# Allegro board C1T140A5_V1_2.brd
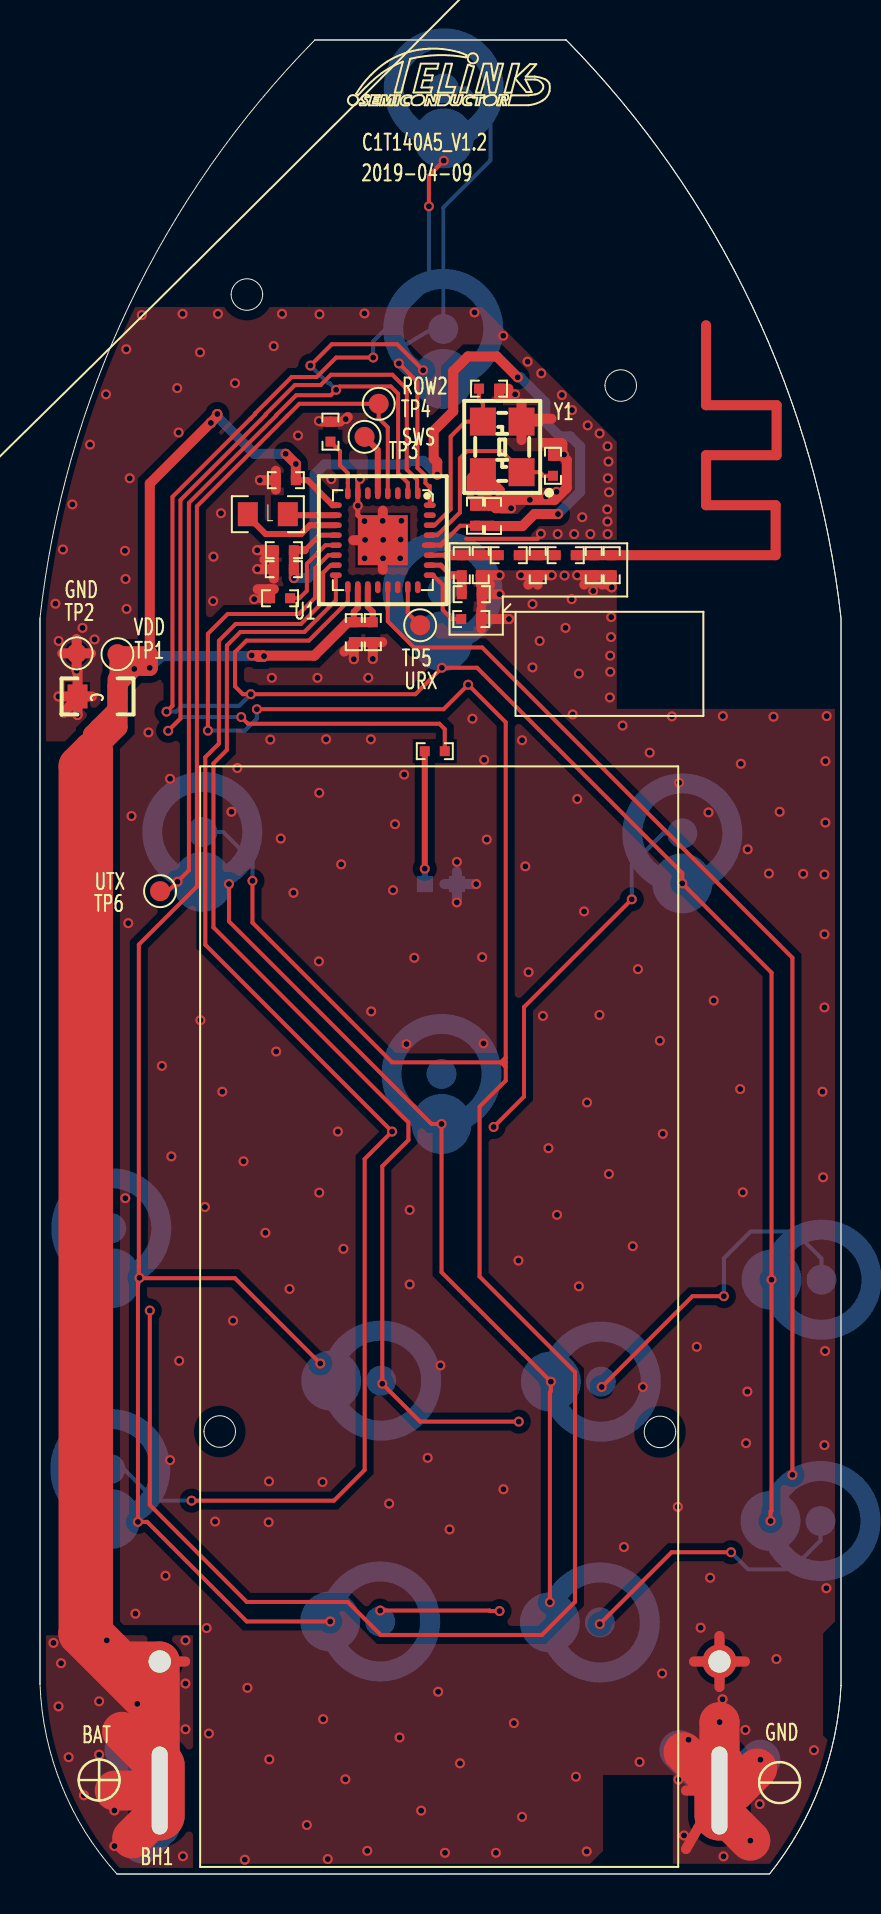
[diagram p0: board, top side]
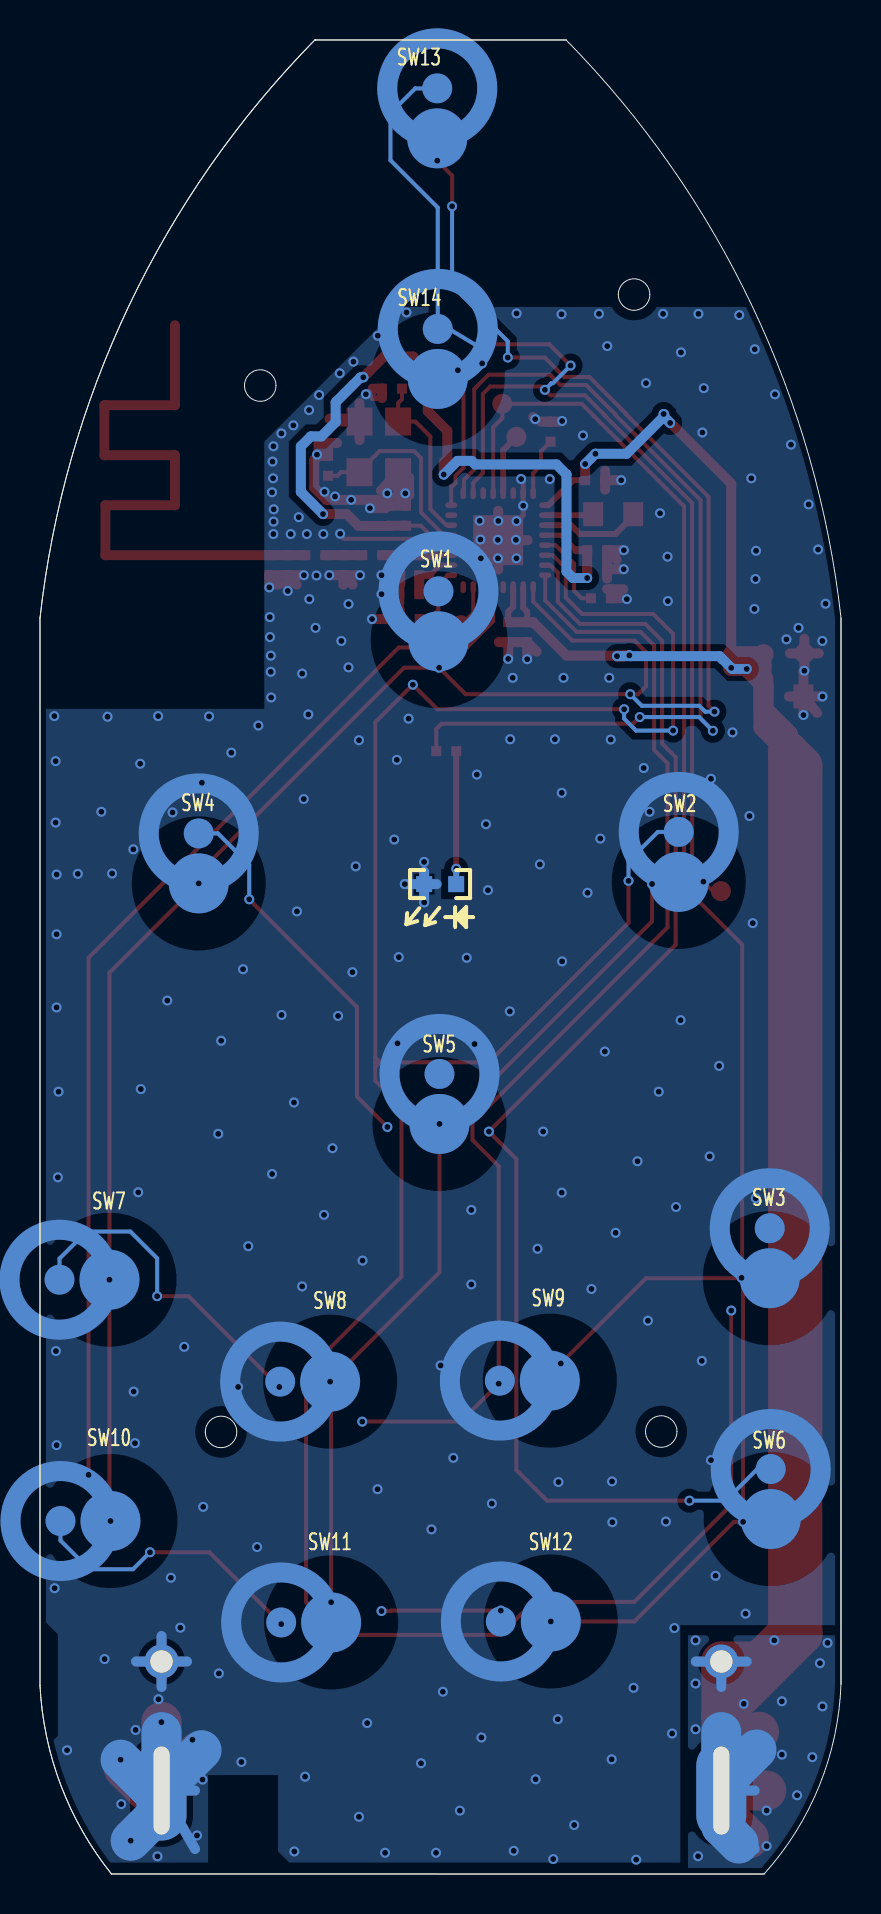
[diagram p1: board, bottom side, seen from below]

Outline 40.07 x 91.71 mm; copper layers: TOP, BOTTOM. Coordinates in mm from the lower left corner of the outline.
Outline path: 0,62.8 0,9.5 ; 0,62.8 arc(4.45,78.41) 13.75,91.71 ; 0,62.8 0,9.5 ; 0,9.5 arc(1.09,4.41) 3.85,0 ; 13.75,91.71 26.29,91.71 ; 13.75,91.71 26.29,91.71 ; 3.85,0 36.49,0 ; 3.85,0 36.49,0 ; 36.49,0 arc(39.02,4.43) 40.07,9.42 ; 36.49,0 arc(39.02,4.43) 40.07,9.42 ; 26.29,91.71 26.32,91.71 ; 26.29,91.71 26.32,91.71 ; 26.32,91.71 arc(35.62,78.41) 40.07,62.8 ; 26.32,91.71 arc(35.62,78.41) 40.07,62.8 ; 40.07,62.8 40.07,9.42 ; 40.07,62.8 40.07,9.42 ; 8.21,22.13 arc(8.99,22.91) 9.78,22.13 arc(8.99,21.34) 8.21,22.13 ; 9.56,78.98 arc(10.35,79.77) 11.14,78.98 arc(10.35,78.2) 9.56,78.98 ; 28.26,74.43 arc(29.05,75.22) 29.84,74.43 arc(29.05,73.65) 28.26,74.43 ; 30.23,22.11 arc(31.01,22.9) 31.8,22.11 arc(31.01,21.32) 30.23,22.11

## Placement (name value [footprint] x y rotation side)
BH1  BATT CON 2xAAA  [BAT]  5.99 4.17 0 top
C1  0.1uF  [0402]  21.76 67.92 270 top
C2  2.2uF  [0402]  22.66 67.91 270 top
C3  2.7pF  [0402]  22.05 65.45 90 top
C4  2pF  [0402]  24.9 65.45 90 top
C5  0.5pF  [0402]  27.7 65.45 90 top
C6  220pF  [0402]  23.45 65.95 0 top
C7  18pF  [0402]  21.6 64 0 top
C8  1uF  [0402]  21.57 62.76 0 top
C9  1uF  [0402]  16.65 62.1 270 top
C10  1uF  [0402]  14.53 72.13 270 top
C11  1uF  [0402]  15.7 62.1 270 top
C12  NC  [0402]  25.66 70.42 90 top
C13  NC  [0402]  22.46 74.28 0 top
C14  1uF  [0402]  12.3 69.7 180 top
C15  1uF  [0402]  12.01 63.8 180 top
C16  0.1uF  [0402]  12.2 66.2 180 top
C17  1uF  [0402]  12.2 65.25 180 top
C19  22uF  [0805C]  2.88 58.89 180 top
D1  LED  [0603-LED]  20.05 49.5 0 bottom
L1  1.3nH  [0402]  21.1 65.45 90 top
L2  3.3nH  [0402]  26.3 65.95 0 top
L3  3.3nH  [0402]  28.6 65.45 270 top
L4  47uH  [0805L]  11.4 68 0 top
R1  1K  [0402]  19.75 56.15 0 top
SW1  SW2PIN_2.2x4.0  [SW_OUT6_IN3_NEW]  20.14 61.64 180 bottom
SW2  SW2PIN_2.2x4.0  [SW_OUT6_IN3_NEW]  8.12 49.61 180 bottom
SW3  SW2PIN_2.2x4.0  [SW_OUT6_IN3_NEW]  3.57 29.79 180 bottom
SW4  SW2PIN_2.2x4.0  [SW_OUT6_IN3_NEW]  32.13 49.54 180 bottom
SW5  SW2PIN_2.2x4.0  [SW_OUT6_IN3_NEW]  20.09 37.51 180 bottom
SW6  SW2PIN_2.2x4.0  [SW_OUT6_IN3_NEW]  3.52 17.75 180 bottom
SW7  SW2PIN_2.2x4.0  [SW_OUT6_IN3_NEW]  36.59 29.72 90 bottom
SW8  SW2PIN_2.2x4.0  [SW_OUT6_IN3_NEW]  25.56 24.62 90 bottom
SW9  SW2PIN_2.2x4.0  [SW_OUT6_IN3_NEW]  14.57 24.67 90 bottom
SW10  SW2PIN_2.2x4.0  [SW_OUT6_IN3_NEW]  36.54 17.65 90 bottom
SW11  SW2PIN_2.2x4.0  [SW_OUT6_IN3_NEW]  25.51 12.58 90 bottom
SW12  SW2PIN_2.2x4.0  [SW_OUT6_IN3_NEW]  14.52 12.63 90 bottom
SW13  SW2PIN_2.2x4.0  [SW_OUT6_IN3_NEW]  20.2 86.79 180 bottom
SW14  SW2PIN_2.2x4.0  [SW_OUT6_IN3_NEW]  20.17 74.76 180 bottom
TP1  VDD  [TP100]  3.87 61 0 top
TP2  GND  [TP100]  1.83 61.04 0 top
TP3  SWS  [TP100]  16.24 71.87 0 top
TP4  Row2  [TP100]  16.94 73.52 0 top
TP5  URX  [TP100]  19.02 62.45 0 top
TP6  UTX  [TP100]  6.01 49.15 0 top
U1  TLSR8258F512ET32  [QFN_5X5_32PIN_0P5_2P50X2P50]  17.15 66.7 270 top
Y1  24Mhz - 12pf - +/-20ppm  [OSCCC250X320X110]  23.12 71.37 180 top

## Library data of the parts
BH1 = Chicony Battery conn 2xAA_0
C1 C6 C9 C11 C14-C16 = C1005X5R1C104K
C2 = C1005X5R1A225K
C3-C5 = C1608_NC
C7 = C1005C0G1H100D
C8 C10 = C1005X5R1C105K
C12 C13 = C1005_NC
C17 = C1005X5R0J475M
C19 = C2012X5R1A226M
D1 = 0603D_Red
L1 L2 = MLK1608_000R
L3 = MLK1005_000R
L4 = IND_0
R1 = RS0402K472JT
SW1 = SW2PIN_8
SW2-SW4 SW6-SW14 = SW2PIN_4
SW5 = SW2PIN_5
TP1-TP6 = TestPad100
U1 = TLSR8258F512ET32
Y1 = OSC_25x32_4pin: Tolerance: RichardLC

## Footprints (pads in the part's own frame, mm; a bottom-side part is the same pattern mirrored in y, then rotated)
0402
  rect 0.5x0.5 smd: 1(-0.5,0) 2(0.5,0)
0603-LED
  rect 0.8x0.8 smd: A(-0.8,0) C(0.8,0)
0805C
  rect 1x1.2 smd: 1(-1,0) 2(1,0)
0805L
  rect 1x1.2 smd: 1(-1,0) 2(1,0)
BAT
  oval 2.5x5 hole 0.8x4.4: 1(0,0) 2(28,0)
  round 1.7 hole 1.118: 3(0,6.454) 4(28,6.454)
OSCCC250X320X110
  rect 1.3x1.4 smd: 1(-0.965,1.265) 2(-0.965,-1.265) 3(0.965,-1.265) 4(0.965,1.265)
QFN_5X5_32PIN_0P5_2P50X2P50
  oval 0.6x0.28 smd: 1(-2.35,1.75) 2(-2.35,1.25) 3(-2.35,0.75) 4(-2.35,0.25) 5(-2.35,-0.25) 6(-2.35,-0.75) 7(-2.35,-1.25) 8(-2.35,-1.75) 17(2.35,-1.75) 18(2.35,-1.25) 19(2.35,-0.75) 20(2.35,-0.25) 21(2.35,0.25) 22(2.35,0.75) 23(2.35,1.25) 24(2.35,1.75)
  oval 0.28x0.6 smd: 9(-1.75,-2.35) 10(-1.25,-2.35) 11(-0.75,-2.35) 12(-0.25,-2.35) 13(0.25,-2.35) 14(0.75,-2.35) 15(1.25,-2.35) 16(1.75,-2.35) 25(1.75,2.35) 26(1.25,2.35) 27(0.75,2.35) 28(0.25,2.35) 29(-0.25,2.35) 30(-0.75,2.35) 31(-1.25,2.35) 32(-1.75,2.35)
  rect 2.5x2.5 smd: 33(0,0)
SW_OUT6_IN3_NEW
  round 3 smd: 1(0,0)
  custom 1.5x1.5 smd: 2(0,2.5)
TP100
  round 1 smd: 1(0,0)

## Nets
1V2: C1.2 C2.2 C16.1 C17.1 U1.12(VDD1V2) U1.28(AVDD1V2)
GND: BH1.2(NEG) BH1.4(NEG1) C1.1 C2.1 C3.1 C4.1 C5.1 C7.2 C8.2 C9.2 C10.1 C11.2 C12.2 C13.2 C14.2 C15.2 C16.2 C17.2 C19.2 D1.C(CATHODE) L3.2 TP2.1(TP) U1.7(DVSS) U1.33(GND) Y1.2 Y1.4
TL_COL0: SW1.2 SW2.2 SW3.2 U1.14(SDMP0/P4/B[4])
TL_COL1: SW4.2 SW5.2 SW6.2 U1.15(SDMN0/P5/B[5])
TL_COL2: SW7.2 SW8.2 SW9.2 U1.16(SDMP1/DI/URTS/B[6])
TL_COL3: SW10.2 SW11.2 SW12.2 U1.21(I2C_SCK/P1N/P0/C[1])
TL_COL4: SW13.2 SW14.2 U1.32(P1N/I2S_SDI/7816_TRX/D[3])
TL_LED: R1.2 U1.1(SWM/I2S_SDO/P2N/D[4])
TL_ROW0: SW1.1 SW4.1 SW7.1 SW10.1 SW13.1 U1.17(SDMN1/DO/URX/B[7])
TL_ROW1: SW2.1 SW5.1 SW8.1 SW11.1 SW14.1 TP6.1(TP) U1.2(CK/I2S_BCK/7816_TRX/D[7])
TL_ROW2: SW3.1 SW6.1 SW9.1 SW12.1 TP4.1(TP) U1.4(DMIC_CLK/7816_CLK/I2S_CLK/A[1])
TL_SWS: TP3.1(TP) U1.5(SWS/URTS/A[7])
TL_URX: TP5.1(TP) U1.23(P1/URX/I2C_SCK/32KIN/C[3])
TL_VDD3: BH1.1(POS) BH1.3(POS1) C9.1 C11.1 C14.1 C19.1 TP1.1(TP) U1.9(VDD_IO) U1.18(VDD3) U1.19(VDDIO_AMS)
TL_XC01: C12.1 U1.29(XC1) Y1.1
TL_XC02: C13.1 U1.30(XC2) Y1.3
N21091199: C3.2 C6.1 L1.2 U1.27(ANT)
N21091201: C7.1 L1.1 U1.26(VANT)
N21091237: C5.2 L2.2 L3.1
N21091295: C4.2 C6.2 L2.1
N21091335: C8.1 U1.25(RESETB)
N21091386: C10.2 U1.8(VDD1V)
N21091449: L4.1 U1.11(VDCDC)
N21091455: L4.2 U1.10(VDCDC_SW)
N21091487: C15.1 U1.13(VDD_F)
N21100596: D1.A(ANODE) R1.1

Pads without a net: U1 3 6 20 22 24 31

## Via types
v1: diameter 0.5, hole 0.3, TOP to BOTTOM, 315 vias

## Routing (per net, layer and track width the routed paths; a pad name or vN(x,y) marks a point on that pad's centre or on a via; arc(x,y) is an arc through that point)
1V2: length 42.5
  TOP w0.2: C1.2 21.02,67.42 20.22,66.63
  TOP w0.25: 13.25,66.2 14,66.95 U1.12 ; 19.22,66.45 U1.28 20.04,66.45 20.22,66.63
  TOP w0.4: 13.25,66.2 C16.1
  TOP w0.5: v1(12.7,64.81) C17.1 C16.1 ; v1(23.89,74.85) 22.85,75.89 21.4,75.89 20.67,75.15 20.67,73.15 19.69,72.17 19.69,70.78 19.87,70.6 v1(19.87,69.98) ; C1.2 22.65,67.42 C2.2 24.13,67.41 24.73,68.01 v1(25.91,68.01)
  BOTTOM w0.5: v1(19.87,69.98) 19.19,70.67 18.48,70.67 18.3,70.49 14.23,70.49 13.73,69.99 13.73,65.13 13.41,64.81 v1(12.7,64.81) ; v1(23.89,74.85) 24.03,74.85 25.28,73.6 25.28,72.6 25.99,71.89 26.52,71.89 27.02,71.39 27.02,69.12 v1(25.91,68.01)
GND: length 117.4
  TOP w0.2: 21.32,66.77 24.91,66.77
  TOP w0.25: U1.33 15.9,67.95 v1(15.9,68.42) U1.7 15.9,69.76 16.04,69.9
  TOP w0.3: 22.96,73.81 23.43,73.81 23.54,73.92 23.37,74.08
  TOP w0.5: 32.31,4.17 BH1.2 32.31,1.25 ; 24.43,64.48 C4.1 ; C4.1 v1(24.06,64.95) ; C4.1 24.9,64.48 ; C4.1 v1(25.6,64.95) ; 11.7,64.25 10.89,64.25 ; C9.2 v1(16.65,60.76) ; C9.2 16.18,61.6 ; C9.2 17.12,61.6 ; 27.7,64.48 C5.1 ; C5.1 L3.2 ; C5.1 v1(26.87,64.95) ; C5.1 27.23,64.48 ; 15.68,66.7 U1.33 ; U1.33 17.15,65.23 ; U1.33 17.15,68.17 ; C8.2 22.07,63.23 ; C8.2 v1(23.46,62.76) ; C8.2 22.07,62.28 ; C2.1 22.66,68.88 ; C2.1 22.65,68.42 C1.1 ; C2.1 23.13,68.41 ; 22.77,68.83 22.77,68.33 22.8,68.3 v1(23.56,68.3) 23.22,68.64 ; 22.77,68.83 22.96,68.64 23.22,68.64 ; 22.77,68.83 22.77,69.18 22.38,69.57 22.38,70.24 22.08,70.24 22.05,70.27 ; C1.1 21.76,68.89 ; C1.1 22.23,68.89 ; TP2.1 v1(1.83,60.17) 1.88,60.13 C19.2 ; TP2.1 1.83,61.76 ; TP2.1 1.11,61.04 ; TP2.1 2.56,61.04 ; L3.2 28.13,64.48 ; L3.2 28.36,64.48 ; L3.2 v1(28.6,64.34) ; C7.2 v1(22.99,64) ; C7.2 22.1,64.47 ; C7.2 22.1,63.53 ; 23.22,68.64 23.22,68.72 v1(24.5,68.72) 25.75,68.72 26.35,69.32 26.35,70.7 26.13,70.92 ; 22.96,73.81 C13.2 23.43,74.28 ; 26.13,70.92 26.13,71.51 26.08,71.56 25.21,71.56 ; 26.13,70.92 C12.2 25.66,71.39 ; C19.2 2.6,58.89 ; C19.2 v1(1.88,57.96) ; C19.2 1.19,58.06 ; C19.2 v1(0.93,58.89) ; 11.51,64.27 C15.2 11.04,63.8 ; 15,72.63 C10.1 14.06,72.63 ; 15.23,61.13 C11.2 ; C11.2 16.17,61.6 ; C11.2 v1(15.7,60.75) ; 21.6,68.95 21.6,68.96 21.6,69.83 22.05,70.27 ; 22.05,70.27 22.05,69.17 ; C14.2 v1(11,69.7) ; C14.2 11.8,70.17 ; C14.2 11.8,69.23 ; Y1.2 24.96,72.63 ; Y1.2 24.09,71.71 ; Y1.2 24.09,73.55 ; 22.16,69.18 Y1.4 23.01,69.18 ; C17.2 11.7,65.72 ; C17.2 11.7,64.78 ; C17.2 v1(10.87,65.25) ; C3.1 v1(22.99,64.95) ; C3.1 22.52,64.48 ; C3.1 22.05,64.48 ; 24.31,72.77 25.59,72.77 ; 11.23,65.73 C16.2 ; C16.2 11.7,65.73 ; C16.2 v1(10.86,66.2) ; 32.71,10.63 BH1.4 ; BH1.4 33.99,11.9 ; BH1.4 33.99,9.35 ; BH1.4 35.26,10.63 ; v1(15.3,72.75) 15.4,72.86
  TOP w2: 33.99,4.29 32.18,6.09 ; 33.99,4.29 BH1.2 ; 33.99,4.29 33.99,7.59 v1(34,7.6) ; v1(35.53,1.67) 33.99,3.21 BH1.2 ; BH1.2 34.77,4.17 35.87,5.28
  BOTTOM w0.5: BH1.4 33.99,11.9 ; BH1.4 35.26,10.63 ; BH1.4 32.71,10.63 ; BH1.4 33.99,9.35 ; 32.31,1.25 BH1.2 32.31,4.17 ; D1.C 20.85,50.12 ; D1.C 20.23,49.5 ; D1.C v1(20.85,48.59) ; D1.C v1(21.82,49.5)
  BOTTOM w2: v1(36.04,5.72) 34.49,4.17 BH1.2 ; 33.99,4.19 33.99,7.1 ; 33.99,4.19 BH1.2 ; 33.99,4.19 31.99,6.19 ; BH1.2 33.99,3.21 v1(35.53,1.67)
  vias: v1(0.77,63.52) v1(0.94,61.66) v1(1.15,66.24) v1(1.62,68.49) v1(2.13,62.31) v1(2.5,71.48) v1(2.73,61.74) v1(3.3,73.99) v1(4.25,66.17) v1(4.28,64.76) v1(4.27,33.8) v1(4.32,76.25) v1(4.33,63.26) v1(4.49,69.8) v1(4.41,47.55) v1(4.58,52.91) v1(4.77,13.02) v1(5.09,77.96) v1(5.43,57.09) v1(6.1,40.41) v1(6.28,14.91) v1(6.51,54.77) v1(6.57,35.89) v1(6.51,20.7) v1(6.86,74.3) v1(6.93,72.09) v1(6.96,25.66) v1(7.13,78.02) v1(8.01,76.09) v1(8.02,42.7) v1(8.25,33.35) v1(8.33,12.3) v1(8.45,7.02) v1(8.68,65.88) v1(8.66,63.65) v1(8.76,17.63) v1(8.9,78.02) v1(9.05,68.05) v1(9.12,39.12) v1(9.58,53.12) v1(9.66,27.67) v1(9.76,74.55) v1(9.87,55.31) v1(10.18,35.64) v1(10.25,0.72) v1(10.38,9.31) v1(10.71,63.75) v1(11.28,32.06) v1(11.46,19.63) v1(11.44,17.59) v1(11.47,5.73) v1(11.6,59.82) v1(11.52,56.73) v1(11.69,76.41) v1(11.81,41.13) v1(12.04,51.78) v1(12.11,78.02) v1(12.48,29.26) v1(12.68,49.07) v1(12.91,71.94) v1(13.35,2.45) v1(13.88,59.82) v1(13.98,78) v1(13.95,72.66) v1(13.97,54.07) v1(13.95,45.64) v1(13.97,34.07) v1(14.13,19.6) v1(14.17,7.74) v1(14.31,56.75) v1(14.4,0.75) v1(14.57,69.75) v1(14.9,37.13) v1(15.06,50.49) v1(15.18,31.26) v1(15.28,4.74) v1(16,69.76) v1(16.23,78.04) v1(16.23,67.66) v1(16.26,66.72) v1(16.24,65.79) v1(16.37,1.16) v1(16.42,59.82) v1(16.55,56.75) v1(16.57,43.14) v1(17.14,67.66) v1(17.17,66.72) v1(17.16,65.79) v1(17.47,18.52) v1(17.66,49.2) v1(17.76,52.5) v1(17.99,6.83) v1(18.08,67.67) v1(18.04,66.73) v1(18.02,65.79) v1(18.22,54.98) v1(18.33,41.51) v1(18.49,33.21) v1(18.49,29.48) v1(18.72,45.82) v1(19.07,3.17) v1(19.39,20.81) v1(19.92,9.11) v1(20.03,25.43) v1(20.26,1.06) v1(20.49,17.23) v1(20.86,50.61) v1(21.01,5.54) v1(21.63,57.77) v1(21.74,78.09) v1(21.8,69.04) v1(22.12,45.85) v1(22.19,41.54) v1(22.22,55.72) v1(22.35,51.73) v1(22.7,69.04) v1(22.81,1.06) v1(23.17,76.93) v1(23.18,19.24) v1(23.77,74) v1(23.71,7.55) v1(23.93,30.68) v1(24.11,56.7) v1(24.11,2.86) v1(24.28,50.39) v1(24.39,75.63) v1(24.44,45.1) v1(24.64,63.51) v1(24.64,60.34) v1(25,61.66) v1(25.08,75.05) v1(25.05,67.02) v1(25.16,42.91) v1(25.31,68.88) v1(25.44,36.3) v1(25.84,69.12) v1(25.9,67.01) v1(25.86,32.96) v1(26.11,73.96) v1(26.21,70.98) v1(26.24,64.93) v1(26.29,62.32) v1(26.6,63.75) v1(26.61,73.21) v1(26.65,57.99) v1(26.72,67.01) v1(26.87,53.76) v1(26.81,4.87) v1(26.96,60.03) v1(26.96,29.39) v1(27.13,67.85) v1(27.22,48.14) v1(27.4,72.44) v1(27.36,38.58) v1(27.35,1.13) v1(27.53,67.01) v1(27.67,64.16) v1(27.99,72.04) v1(27.99,42.96) v1(28.39,71.4) v1(28.38,68.24) v1(28.39,67.63) v1(28.4,67.01) v1(28.44,70.63) v1(28.41,69.8) v1(28.46,69.1) v1(28.46,35) v1(28.57,62.85) v1(28.56,61.86) v1(28.52,60.93) v1(28.53,60.12) v1(28.51,58.84) v1(29.14,57.43) v1(29.21,16.35) v1(29.65,31.39) v1(29.91,45.25) v1(29.99,5.6) v1(30.16,24.36) v1(30.5,56.08) v1(31.01,41.67) v1(31.15,37.01) v1(31.12,10.03) v1(31.61,57.89) v1(31.97,54.57) v1(31.91,18.36) v1(31.94,4.72) v1(32.22,1.93) v1(32.44,6.71) v1(32.85,26.36) v1(33.05,12.32) v1(33.44,53.09) v1(33.52,14.81) v1(33.7,43.68) v1(34.16,57.91) v1(34.14,8.74) v1(34.19,0.88) v1(35.06,55.52) v1(35.03,39.25) v1(35.16,34.09) v1(35.29,7.2) v1(35.38,24.13) v1(35.32,21.54) v1(35.4,51.24) v1(36.01,3.5) v1(36.46,50.03) v1(36.69,57.87) v1(36.84,10.75) v1(37,53.12) v1(38.18,50.02) v1(38.72,6.19) v1(39.14,39.12) v1(39.17,34.84) v1(39.29,55.65) v1(39.29,52.58) v1(39.24,49.98) v1(39.24,46.99) v1(39.24,43.34) v1(39.27,26.15) v1(39.24,21.45) v1(39.35,57.9) v1(39.34,14.29)
TL_COL0: length 133.9
  TOP w0.2: U1.14 14.42,65.95 13.77,65.3 13.77,63.83 12.95,63.01 9.39,63.01 8.4,62.02 v1(8.4,57.18) ; 23.05,40.59 17.61,40.59 10.63,47.57 v1(10.63,49.66) ; 23.05,40.59 23.3,40.84 ; 23.05,40.59 23.06,40.59 ; 23.3,40.59 23.3,40.35 ; 23.3,40.59 23.3,40.84 ; 23.3,40.59 23.06,40.59 ; 23.3,40.35 23.3,39.68 21.99,38.37 21.99,29.88 26.76,25.11 26.76,13.61 25.11,11.96 17.04,11.96 15.39,13.61 10.34,13.61 5.49,18.46 v1(5.49,28.18) ; 23.3,40.35 23.06,40.59 ; 23.3,40.84 23.3,57.59 v1(21.42,59.47) 20.19,58.25 v1(10.85,58.25)
  BOTTOM w0.2: v1(10.85,58.25) 10.85,57.78 10.25,57.18 v1(8.4,57.18) ; SW2.2 9.16,52.11 10.63,50.64 v1(10.63,49.66)
TL_COL1: length 87.6
  TOP w0.2: v1(29.6,48.74) 24.21,43.35 24.21,38.88 v1(22.69,37.36) ; v1(7.58,18.67) 14.7,18.67 16.24,20.21 16.24,35.76 v1(17.61,37.13) 8.27,46.47 8.27,55.85 8.95,56.53 8.95,61.67 9.79,62.51 13.06,62.51 14.17,63.62 14.17,65.08 14.54,65.45 U1.15
  BOTTOM w0.2: SW6.2 4.19,20.25 5.77,18.67 v1(7.58,18.67) ; v1(29.6,48.74) 29.6,50.47 31.17,52.04 SW4.2
TL_COL2: length 74
  TOP w0.2: U1.16 14.8,63.69 13.22,62.11 10.03,62.11 9.35,61.44 9.35,56.21 8.68,55.54 8.68,47.34 18.43,37.58 18.43,36.7 17.12,35.4 v1(17.12,24.52) 19.02,22.62 v1(23.95,22.62) ; v1(34.21,28.9) 32.64,28.9 v1(28.1,24.35)
  BOTTOM w0.2: v1(34.21,28.9) 34.21,30.79 35.55,32.13 37.74,32.13 39.09,30.77 SW7.2
TL_COL3: length 75.8
  TOP w0.2: v1(34.57,16.09) 31.59,16.09 v1(28,12.5) ; v1(22.99,13.15) 22.52,13.15 22.49,13.17 v1(17.02,13.17) ; v1(37.64,19.96) 37.64,45.82 22.12,61.34 18.71,61.34 17.4,62.64 U1.21
  BOTTOM w0.2: v1(34.57,16.09) 35.42,15.24 37.61,15.24 39.04,16.68 SW10.2 ; SW12.2 v1(17.02,13.17)
TL_COL4: length 25.6
  TOP w0.2: U1.32 19.5,69.41 19.43,69.41 19.28,69.56 19.28,69.92 18.88,70.32 18.88,74.61 v1(17.95,75.54)
  BOTTOM w0.2: v1(17.95,75.54) 17.95,76.27 19.61,77.26 SW14.2 20.17,83.34 22.54,85.7 22.54,88.05 21.3,89.29 SW13.2
TL_LED: length 46.9
  TOP w0.2: v1(10.07,57.86) 10.4,57.52 19.98,57.52 20.25,57.25 R1.2 ; U1.1 18.86,69.09 18.86,69.72 18.35,70.23 18.35,74.25 17.63,74.97 14.55,74.97 14.04,74.46 12.75,74.46 11.28,72.99 11.28,72.96 7.03,68.71 7.03,57.79 v1(6.41,57.17)
  BOTTOM w0.2: v1(6.41,57.17) 7.1,57.86 v1(10.07,57.86)
TL_ROW0: length 112.9
  TOP w0.2: U1.17 15.4,63.63 13.45,61.68 10.33,61.68 9.76,61.11 9.76,59.39 10.15,59 v1(10.55,59) 18.78,59 v1(20.1,60.32) 21.86,60.32 32.13,50.05 v1(32.13,49.54) 36.59,45.07 v1(36.59,29.72) 36.59,18.17 36.54,18.12 v1(36.54,17.65) ; v1(20.2,85.68) 19.46,84.94 v1(19.46,83.4) ; v1(6.33,58.13) 6.63,58.42 6.63,68.87 10.53,72.77 10.77,73.01 10.76,73.02 10.76,73.02 10.75,73.03 12.59,74.86 13.84,74.86 14.82,75.83 v1(16.67,75.83)
  BOTTOM w0.2: v1(6.33,58.13) 6.8,58.13 7.09,58.42 9.96,58.42 v1(10.55,59) ; v1(16.67,75.83) 16.67,76.65 19.46,79.43 v1(19.46,83.4) ; SW13.1 v1(20.2,85.68) ; SW1.1 20.1,61.61 v1(20.1,60.32)
TL_ROW1: length 94.6
  TOP w0.2: v1(13.53,75.43) 14.6,76.5 17.86,76.5 v1(19.17,75.2) ; v1(9.45,49.51) 9.45,47.64 19.58,37.51 v1(20.09,37.51) 20.09,30.09 v1(25.56,24.62) 25.56,24.15 25.51,24.1 v1(25.51,13.59) ; TP6.1 6.41,49.15 v1(6.88,49.62) 7.45,50.19 7.45,68.56 11.82,72.93 11.82,72.96 12.81,73.95 14.54,73.95 v1(14.81,74.22) 14.98,74.39 17.55,74.39 17.92,74.02 17.92,70.05 18.4,69.57 U1.2
  BOTTOM w0.2: v1(19.17,75.2) 19.6,74.76 SW14.1 ; v1(14.81,74.22) 14.48,74.55 14.41,74.55 v1(13.53,75.43) ; v1(25.51,13.59) SW11.1 ; v1(9.45,49.51) 9.35,49.61 SW2.1 8.11,49.62 v1(6.88,49.62)
TL_ROW2: length 94.4
  TOP w0.2: 4.94,29.81 4.94,30.37 4.95,30.4 4.95,46.48 7.85,49.38 7.85,68.4 12.35,72.89 12.35,72.89 12.97,73.52 TP4.1 16.94,72.8 17.4,72.34 U1.4 ; 4.94,29.81 4.96,29.79 9.76,29.79 v1(14.02,25.53) ; 4.94,29.81 4.97,29.81 v1(4.98,29.81) 4.98,29.73 4.9,29.65 v1(4.9,17.61) 5.36,17.61 10.34,12.63 v1(14.52,12.63)
  BOTTOM w0.2: SW9.1 14.02,25.22 v1(14.02,25.53) ; v1(4.9,17.61) 4.71,17.61 4.57,17.75 SW6.1 ; SW3.1 4.96,29.79 v1(4.98,29.81)
TL_SWS: length 3.1
  TOP w0.2: 16.88,71.23 16.9,71.23
  TOP w0.3: TP3.1 16.88,71.23 ; 16.9,71.23 U1.5
TL_URX: length 2.2
  TOP w0.2: TP5.1 18.4,63.07 U1.23
TL_VDD3: length 197.2
  TOP w0.3: C11.1 15.7,63.12 15.9,63.32 U1.18 ; C14.1 13.39,69.7 14.64,68.45 U1.9 ; U1.19 16.4,63.37 16.65,63.12 C9.1
  TOP w0.5: v1(11.21,60.9) 11.17,60.86 11.15,60.86 ; 4.99,9.62 BH1.3 7.26,10.63 ; 11.15,60.86 10.93,60.86 10.85,60.94 ; 11.15,60.86 11.17,60.89 11.17,60.93 ; v1(8.87,73.01) 8.87,72.91 8.55,72.59 ; v1(8.55,72.56) 8.55,72.59 ; 8.55,72.59 5.49,69.53 5.49,61.01 ; 10.85,60.94 v1(10.59,60.94) ; 10.85,60.94 11.15,60.94 11.17,60.93 ; 11.17,60.93 13.72,60.93 15.4,62.6 C11.1 C9.1 ; v1(12.29,71.02) v1(12.8,70.51) C14.1 ; v1(4.72,60.26) 5.44,60.26 v1(5.49,60.32) ; 4.3,60.26 3.88,59.84 ; 4.31,7.1 BH1.1 4.31,1.25
  TOP w0.8: v1(4.72,60.26) 4.61,60.26 ; v1(4.72,60.26) 3.88,59.42 ; v1(4.72,60.26) 4.77,60.32 v1(5.49,60.32) 5.49,61.01 5.48,61 TP1.1 ; 4.61,60.26 4.02,60.26 3.88,60.4 ; 4.61,60.26 TP1.1 ; TP1.1 3.88,60.4 ; 3.88,59.74 3.88,60.4
  TOP w1: 3.88,59.74 C19.1 3.88,58.2 ; 2.98,57.3 3.88,58.2 ; 2.98,57.3 2.65,56.97 2.65,56.12 2.98,56.45 ; 2.98,57.3 2.98,56.45 ; 3.88,58.2 3.88,57.35 2.98,56.45
  TOP w2: 2.65,12.07 4.1,10.63 BH1.3 5.99,7.92 ; 2.65,12.07 2.65,56.12 1.93,55.41 1.93,12.07 ; 2.65,12.07 1.93,12.07 ; 4.61,1.78 5.99,3.16 BH1.1 ; BH1.1 3.74,4.17 ; BH1.1 5.99,5.23 ; 5.99,5.23 4.1,7.11 ; 5.99,5.23 5.99,7.92 ; 5.99,7.92 1.93,11.97 1.93,12.07
  BOTTOM w0.5: 4.31,4.17 BH1.1 4.31,1.25 ; 10.55,60.9 6.09,60.9 5.94,60.75 5.93,60.75 v1(5.49,60.32) 5.44,60.26 v1(4.72,60.26) ; 10.55,60.9 v1(10.59,60.94) ; 10.55,60.9 v1(11.21,60.9) ; 4.71,10.63 BH1.3 ; BH1.3 7.26,10.63 ; BH1.3 5.99,9.35 ; v1(8.55,72.56) 8.85,72.86 8.85,72.9 ; v1(8.87,73.01) 8.85,72.99 8.85,72.9 ; 8.85,72.9 10.73,71.02 v1(12.29,71.02) v1(12.8,70.51)
  BOTTOM w2: 5.99,4.46 5.99,7.1 ; 5.99,4.46 BH1.1 5.99,2.39 5.12,1.52 ; 5.99,4.46 4.23,6.22
  vias: v1(0.67,11.56) v1(0.93,8.38) v1(1.05,10.54) v1(1.44,5.84) v1(2.2,3.94) v1(2.96,8.64) v1(2.96,5.97) v1(3.34,11.68) v1(3.72,3.17) v1(3.72,1.4) v1(4.86,8.51) v1(7.15,0.89) v1(7.28,11.68) v1(7.28,9.53) v1(7.28,7.24)
TL_XC01: length 10
  TOP w0.2: C12.1 25.19,69.92 25.01,70.1 Y1.1 24.09,70.15 23.08,71.16 21.36,71.16 21.01,70.8 21.01,68.09 19.87,66.95 U1.29
TL_XC02: length 8.7
  TOP w0.2: C13.1 21.96,73.75 22.16,73.55 Y1.3 21.29,72.63 20.54,71.89 20.54,68.25 19.74,67.45 U1.30
N21091199: length 3.5
  TOP w0.25: 20.41,65.95 U1.27
  TOP w0.5: 20.41,65.95 L1.2 C3.2 C6.1
N21091201: length 2.8
  TOP w0.25: 20.55,64.95 20.05,65.45 U1.26
  TOP w0.4: L1.1 20.55,64.95
  TOP w0.5: C7.1 L1.1
N21091237: length 32
  TOP w0.5: 33.32,77.45 33.32,73.45 36.85,73.45 36.85,70.95 33.32,70.95 33.32,68.45 36.8,68.45 36.8,65.95 L3.1 C5.2 L2.2
N21091295: length 1.8
  TOP w0.5: L2.1 C4.2 C6.2
N21091335: length 3.2
  TOP w0.2: U1.25 19.66,64.95 19.69,64.92 19.69,64.92 20.02,64.6 20.02,64.59 20.14,64.46 20.14,63.22 20.6,62.76 C8.1
N21091386: length 2.9
  TOP w0.2: C10.2 15.01,71.15 15.01,70.45 15.4,70.06 15.4,69.57 U1.8
N21091449: length 5.1
  TOP w0.3: L4.1 10.4,67.9 11.28,67.01 13.06,67.01 13.5,67.45 U1.11
N21091455: length 2.4
  TOP w0.3: L4.2 12.45,67.95 U1.10
N21091487: length 4.2
  TOP w0.2: C15.1 12.98,63.8 13.35,64.17 13.35,65.52 14.28,66.45 U1.13
N21100596: length 6.6
  TOP w0.3: R1.1 v1(19.25,50.27)
  BOTTOM w0.3: v1(19.25,50.27) 19.25,50.18 19.25,50.17 D1.A

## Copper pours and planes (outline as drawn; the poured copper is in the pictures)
GND on TOP: 8.04,0.51 8.04,12.45 3.98,12.45 3.98,56.64 0.3,56.64 0.3,62.79 1.61,69.81 3.94,76.56 4.34,77.46 4.75,78.36 22.11,78.36 23.91,76.56 23.92,76.56 28.85,71.63 28.85,66.71 18.4,66.71 18.4,65.19 28.85,65.19 28.85,58.26 39.77,58.26 39.77,12.63 39.17,12.03 39.17,6.93 39.4,6.7 38.28,3.45 36.51,0.51 31.66,0.51 31.66,4.95 28.16,4.95 28.16,1.16 27.51,0.51 ; 11 cut-outs
GND on BOTTOM: 8.04,0.57 8.04,12.45 0.3,12.45 0.3,60.33 0.3,62.79 1.06,67.5 2.28,72.11 3.41,75.28 4.75,78.36 22.11,78.36 23.91,76.56 23.92,76.56 28.85,71.63 28.85,58.26 39.77,58.26 39.77,12.59 39.17,11.99 39.17,6.91 39.39,6.69 38.3,3.48 36.56,0.57 31.66,0.57 31.66,4.95 28.16,4.95 28.16,1.14 27.6,0.57 ; 1 cut-out
TL_VDD3 on TOP, BOTTOM: 3.98,0.3 1.34,4.58 0.3,9.51 0.3,11.94 7.66,11.94 7.66,0.3

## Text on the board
User.Comments: C4 | C2 | L5
Ref Des/Silkscreen Top: GND | BAT | UTX | VDD | 2019-04-09 | C1T140A5_V1.2 | SWS | ROW2 | URX
COMPVAL_TYPE_TOP: NC | 1.8pF | 1pF | 1.5pF
User.5: FIGURE | SIZE | 0.3 | 1.1176 | 4.4x0.8 | 3.4397x1.829 | DRILL CHART: TOP to BOTTOM | ALL UNITS ARE IN MILLIMETERS | PLATED | NON-PLATED | QTY | 315 | 2 | 1
